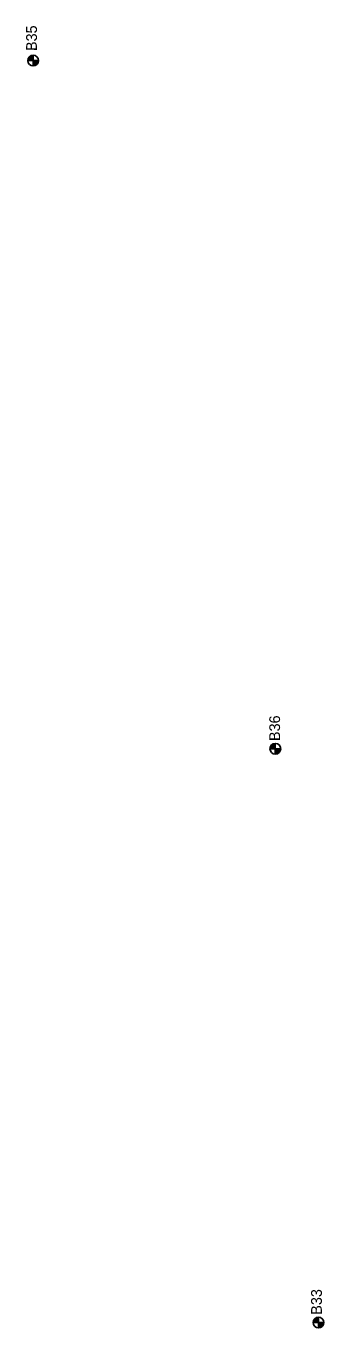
# Model space of a CAD drawing. Extents: x 345549 to 379569, y 127949 to 230467.
# Drawn here: x 361184 to 361461, y 147449 to 148660 of the extents above; entities that cross this region are included whole.
import ezdxf

# ---------------------------------------------------------------- set-up
doc = ezdxf.new("R2010")
doc.units = 0
for name, color, linetype in [('E_SOIL_BORE1 [KAPUR_CADDS_LEVELS]', 7, 'Continuous'), ('E_SOIL_BORE2 [KAPUR_CADDS_LEVELS]', 7, 'Continuous'), ('P_MARK', 7, 'Continuous')]:
    doc.layers.add(name, color=color, linetype=linetype)

msp = doc.modelspace()

# ---------------------------------------------------------------- linework, layer by layer
at = {"layer": 'P_MARK'}
for p, q in [((361185.6, 148628.1), (361195.6, 148628.1)), ((361190.6, 148633.1), (361190.6, 148623.1)), ((361415.8, 147992.9), (361415.8, 147982.9)), ((361410.8, 147987.9), (361420.8, 147987.9)), ((361456, 147459.1), (361456, 147449.1)), ((361451, 147454.1), (361461, 147454.1))]:
    msp.add_line(p, q, dxfattribs=at)
for centre in [(361190.6, 148628.1), (361415.8, 147987.9), (361456, 147454.1)]:
    msp.add_circle(centre, 5, dxfattribs=at)
for centre, radius, start, end in [((361190.6, 148628.1), 4.5, 89.9869, 179.9869), ((361190.6, 148628.1), 4, 89.9869, 179.9869), ((361190.6, 148628.1), 3.5, 89.9869, 179.9869), ((361190.6, 148628.1), 3, 89.9869, 179.9869), ((361190.6, 148628.1), 2.5, 89.9869, 179.9869), ((361190.6, 148628.1), 2, 89.9869, 179.9869), ((361190.6, 148628.1), 1.5, 89.9869, 179.9869), ((361190.6, 148628.1), 1, 89.9869, 179.9869), ((361190.6, 148628.1), 0.5, 89.9869, 179.9869), ((361190.6, 148628.1), 4.5, 269.9869, 359.9869), ((361190.6, 148628.1), 4, 269.9869, 359.9869), ((361190.6, 148628.1), 3.5, 269.9869, 359.9869), ((361190.6, 148628.1), 3, 269.9869, 359.9869), ((361190.6, 148628.1), 2.5, 269.9869, 359.9869), ((361190.6, 148628.1), 2, 269.9869, 359.9869), ((361190.6, 148628.1), 1.5, 269.9869, 359.9869), ((361190.6, 148628.1), 1, 269.9869, 359.9869), ((361190.6, 148628.1), 0.5, 269.9869, 359.9869), ((361415.8, 147987.9), 4.5, 89.9869, 179.9869), ((361415.8, 147987.9), 4, 89.9869, 179.9869), ((361415.8, 147987.9), 3.5, 89.9869, 179.9869), ((361415.8, 147987.9), 3, 89.9869, 179.9869), ((361415.8, 147987.9), 2.5, 89.9869, 179.9869), ((361415.8, 147987.9), 2, 89.9869, 179.9869), ((361415.8, 147987.9), 1.5, 89.9869, 179.9869), ((361415.8, 147987.9), 1, 89.9869, 179.9869), ((361415.8, 147987.9), 0.5, 89.9869, 179.9869), ((361415.8, 147987.9), 4.5, 269.9869, 359.9869), ((361415.8, 147987.9), 4, 269.9869, 359.9869), ((361415.8, 147987.9), 3.5, 269.9869, 359.9869), ((361415.8, 147987.9), 3, 269.9869, 359.9869), ((361415.8, 147987.9), 2.5, 269.9869, 359.9869), ((361415.8, 147987.9), 2, 269.9869, 359.9869), ((361415.8, 147987.9), 1.5, 269.9869, 359.9869), ((361415.8, 147987.9), 1, 269.9869, 359.9869), ((361415.8, 147987.9), 0.5, 269.9869, 359.9869), ((361456, 147454.1), 4.5, 89.9869, 179.9869), ((361456, 147454.1), 4, 89.9869, 179.9869), ((361456, 147454.1), 3.5, 89.9869, 179.9869), ((361456, 147454.1), 3, 89.9869, 179.9869), ((361456, 147454.1), 2.5, 89.9869, 179.9869), ((361456, 147454.1), 2, 89.9869, 179.9869), ((361456, 147454.1), 1.5, 89.9869, 179.9869), ((361456, 147454.1), 1, 89.9869, 179.9869), ((361456, 147454.1), 0.5, 89.9869, 179.9869), ((361456, 147454.1), 4.5, 269.9869, 359.9869), ((361456, 147454.1), 4, 269.9869, 359.9869), ((361456, 147454.1), 3.5, 269.9869, 359.9869), ((361456, 147454.1), 3, 269.9869, 359.9869), ((361456, 147454.1), 2.5, 269.9869, 359.9869), ((361456, 147454.1), 2, 269.9869, 359.9869), ((361456, 147454.1), 1.5, 269.9869, 359.9869), ((361456, 147454.1), 1, 269.9869, 359.9869), ((361456, 147454.1), 0.5, 269.9869, 359.9869)]:
    msp.add_arc(centre, radius, start, end, dxfattribs=at)

# ---------------------------------------------------------------- texts
at = {"layer": 'E_SOIL_BORE1 [KAPUR_CADDS_LEVELS]'}
msp.add_text('B33', height=10, rotation=89.9869, dxfattribs=at).set_placement((361459.1, 147461.4))
at = {"layer": 'E_SOIL_BORE2 [KAPUR_CADDS_LEVELS]'}
for s, p in [('B35', (361194.1, 148637)), ('B36', (361420.2, 147995.1))]:
    msp.add_text(s, height=10, rotation=89.9869, dxfattribs=at).set_placement(p)

doc.saveas('drawing.dxf')
